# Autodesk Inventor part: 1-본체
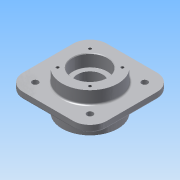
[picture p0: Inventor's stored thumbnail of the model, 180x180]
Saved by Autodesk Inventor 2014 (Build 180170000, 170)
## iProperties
Created: 2015-09
Part Number: 1-본체
Material: 알루미늄 6061
Document SubType Name: Modeling
Designer: study
Density: 2.71 g/cm^3
Appearance: 알루미늄 - 평지
Mass: 1464.68 g
Surface Area: 800.934 cm^2
Volume: 540.471 cm^3
Author: study
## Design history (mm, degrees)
sketch "스케치1"
  geometry: L1 (-75, 75)-(75, 75); L2 (75, 75)-(75, -75); L3 (75, -75)-(-75, -75); L4 (-75, -75)-(-75, 75); L5 (-75, 75)-(75, -75); L6 (75, 75)-(-75, -75); 1 further point
  constraints: 12 end point, 2 midpoint, 2 parallel, 1 horizontal, 1 perpendicular
  dimensions: "d0" = 150 distance of L1.start L1.end; "d1" = 150 distance of L1.end L2.end
extrude "돌출1" new body sketch "스케치1" stored distance "d2" = 12; taper "d3" = 0 deg
node "작업 평면1"
sketch "스케치2"
  geometry: C1 r 50 at (0, 0); 1 further point
  constraints: 1 centre point, 1 coincident
  dimensions: "d5" = 100 diameter of C1
extrude "돌출2" join sketch "스케치2" distance "d6" = 70; taper "d7" = 0 deg
sketch "스케치3"
  geometry: L1 (75, 75)-(-75, 75) reference; L2 (-75, 75)-(-75, -75) reference; L3 (-75, -75)-(75, -75) reference; L4 (75, -75)-(75, 75) reference; L5 (-49, 49)-(49, 49); L6 (49, 49)-(49, -49); L7 (49, -49)-(-49, -49); L8 (-49, -49)-(-49, 49); C1 r 10 at (-49, 49); C2 r 10 at (49, 49); C3 r 10 at (49, -49); C4 r 10 at (-49, -49)
  constraints: 8 end point, 4 centre point, 4 coincident, 3 equal radius, 3 other
  dimensions: "d8" = 98 distance of L5.end L6.end; "d9" = 20 diameter of C1
extrude "돌출3" join sketch "스케치3" distance "d10" = 5; taper "d11" = 0 deg
sketch "스케치4"
  geometry: C1 r 10 at (0, 0) reference; C2 r 10 at (98, 0) reference; C3 r 10 at (98, -98) reference; C4 r 10 at (0, -98) reference; 5 further points
  constraints: 4 coincident
hole "구멍1" sketch "스케치4" at (0, 0), (98, 0), (98, -98), (0, -98) diameter "d12" = 11; stored, may be unused: countersink angle "d16" = 90 deg, drill point angle "d18" = 118 deg; dims "d13" = 6, "d14" = 4, "d15" = 2, "d17" = 8
sketch "스케치5"
  geometry: L1 (28.991, -28.991)-(-28.991, -28.991); L2 (-28.991, -28.991)-(-28.991, 28.991); L3 (-28.991, 28.991)-(28.991, 28.991); L4 (28.991, 28.991)-(28.991, -28.991); C1 r 50 at (0, 0) reference; A1 r 41 centre (0, 0) between (28.991, -28.991) and (28.991, 28.991); 4 further points
  constraints: 8 end point, 4 coincident, 2 point on circle, 1 centre point, 1 point on line, 1 vertical, 9 other
  dimensions: "d19" = 82 diameter of A1
hole "구멍2" sketch "스케치5" at (-28.991, 28.991), (-28.991, -28.991), (28.991, -28.991), (28.991, 28.991) diameter "d20" = 4.917; stored, may be unused: countersink angle "d24" = 90 deg, drill point angle "d26" = 118 deg; dims "d21" = 10, "d22" = 4, "d23" = 2, "d25" = 13
hole "구멍3" diameter "d29" = 45; stored, may be unused: countersink angle "d33" = 90 deg, drill point angle "d35" = 118 deg; dims "d27" = 10, "d28" = 10, "d30" = 10, "d31" = 62, "d32" = 22, "d34" = 13
node "작업 평면2"
sketch "스케치6"
  geometry: C1 r 50 at (0, 0) reference; 1 further point
  constraints: 1 vertical alignment, 1 other
  dimensions: "d36" = 65 distance of C1.centre point (0, 65)
feature "엠보싱1" sketch "스케치6" dims "d0" = 150, "d1" = 150, "d37" = 1, "d38" = 0
fillet "모깎기1" dims "d39" = 30
fillet "모깎기2" dims "d40" = 3, "d41" = 0.3
chamfer "모따기1" distance "d42" = 1; stored, may be unused: second distance "d43" = 2, angle "d44" = 45 deg
node "솔리드1"
mirror "대칭1"
node "투영된 루프1"
node "투영된 루프2"
node "투영된 루프3"
other parameters: "d4" = 23
